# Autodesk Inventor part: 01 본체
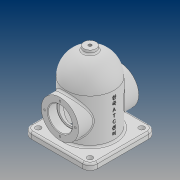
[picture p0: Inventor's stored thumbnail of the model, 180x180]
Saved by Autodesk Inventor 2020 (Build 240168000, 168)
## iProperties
Created: 2021-08
Part Number: 01 본체
Material: 일반
Document SubType Name: Modeling
Designer: PC312-
Density: 1 g/cm^3
Appearance: 기본값
Author: PC312-
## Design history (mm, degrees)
sketch "스케치1"
  geometry: C1 r 40 at (0, 0); 1 further point
  constraints: 1 centre point, 1 coincident
  dimensions: "d0" = 80 diameter of C1
extrude "돌출1" new body sketch "스케치1" distance "d1" = 124; taper "d2" = 0 deg
sketch "스케치2"
  geometry: 1 further point
fillet "모깎기1" dims "d3" = 40
feature "쉘1" dims "d4" = 8
sketch "스케치3"
  geometry: L1 (55, 55)-(-55, 55); L2 (-55, 55)-(-55, -55); L3 (-55, -55)-(55, -55); L4 (55, -55)-(55, 55); L5 (55, 55)-(-55, -55); L6 (-55, 55)-(55, -55); C1 r 40 at (0, 0) reference; 1 further point
  constraints: 12 end point, 2 midpoint, 2 parallel, 1 horizontal, 1 perpendicular
  dimensions: "d5" = 110 distance between parallel lines of L2 L4; "d6" = 110 distance between parallel lines of L3 L1
extrude "돌출2" join sketch "스케치3" distance "d7" = 10; taper "d8" = 0 deg
node "작업 평면1"
sketch "스케치4"
  geometry: L1 (55, 0)-(-55, 0) reference; C1 r 31 at (0, 48); 2 further points
  constraints: 1 centre point, 1 midpoint, 1 vertical alignment
  dimensions: "d10" = 62 diameter of C1; "d11" = 48 distance from line of C1.centre L1
extrude "돌출3" join sketch "스케치4" stored distance "d12" = 10; taper "d13" = 0 deg
sketch "스케치5"
  geometry: C1 r 20 at (0, 0); C2 r 31 at (0, 0) reference; 1 further point
  constraints: 1 centre point, 1 concentric
  dimensions: "d14" = 40 diameter of C1
extrude "돌출4" cut sketch "스케치5" distance "d15" = 15; taper "d16" = 0 deg
sketch "스케치6"
  geometry: C1 r 16.5 at (0, 0); C2 r 20 at (0, 0) reference; 1 further point
  constraints: 1 centre point, 1 concentric
  dimensions: "d17" = 33 diameter of C1
extrude "돌출5" cut sketch "스케치6" extent not by distance; stored distance "d18" = 15; taper "d19" = 0 deg
sketch "스케치7"
  geometry: L1 (55, -48)-(-55, -48) reference; C1 r 31 at (0, 0) reference; 3 further points
  constraints: 1 midpoint, 1 vertical alignment
  dimensions: "d20" = 25.5 distance of C1.centre point (0, 25.5)
hole "구멍1" sketch "스케치7" at (0, 25.5) diameter "d21" = 3.242; stored, may be unused: countersink angle "d25" = 90 deg, drill point angle "d27" = 118 deg; dims "d22" = 8, "d23" = 4, "d24" = 2, "d26" = 10
node "작업 평면2"
sketch "스케치8"
  geometry: C1 r 10 at (0, 0); 1 further point
  constraints: 1 centre point, 1 coincident
  dimensions: "d32" = 20 diameter of C1
extrude "돌출6" join sketch "스케치8" stored distance "d33" = 15; taper "d34" = 0 deg
sketch "스케치9"
  geometry: C1 r 10 at (0, 0) reference; 2 further points
  constraints: 1 coincident
hole "구멍2" sketch "스케치9" at (0, 0) diameter "d35" = 5.1881; stored, may be unused: countersink angle "d39" = 90 deg, drill point angle "d41" = 0 deg; dims "d36" = 12, "d37" = 4, "d38" = 2, "d40" = 70
sketch "스케치10"
  geometry: L1 (55, 55)-(-55, 55) reference; L2 (-55, 55)-(-55, -55) reference; C1 r 4.5 at (-43, 43); 1 further point
  constraints: 1 centre point
  dimensions: "d42" = 9 diameter of C1; "d43" = 12 distance from line of C1.centre L1; "d44" = 12 distance from line of C1.centre L2
extrude "돌출7" cut sketch "스케치10" extent not by distance; stored distance "d45" = 0; taper "d46" = 0 deg
fillet "모깎기2" dims "d53" = 12
fillet "모깎기3" dims "d54" = 3
fillet "모깎기4" dims "d55" = 3
fillet "모깎기5" dims "d56" = 0.3
chamfer "모따기1" distance "d57" = 1; stored, may be unused: second distance "d58" = 2, angle "d59" = 45 deg
node "작업 평면3"
sketch "스케치11"
  geometry: L1 (0, -43)-(0, 43) reference; 2 further points
  constraints: 1 horizontal alignment, 1 other
  dimensions: "d61" = 48 distance from line of point (48, 0) L1
feature "엠보싱1" sketch "스케치11" dims "d1" = 124, "d2" = 0, "d62" = 0.5, "d63" = 0
node "솔리드1"
pattern_circular "원형 패턴1" dims angle "d29" = 360 deg
mirror "미러1"
pattern_linear "직사각형 패턴1" dims "d49" = 86, "d52" = 86
feature "A9D066F2-1C7D-4E18-AEED-F7BC21143FA4" dims "d21" = 3.242, "d22" = 8, "d23" = 4, "d24" = 2, "d25" = 90 deg, "d26" = 10, "d27" = 118 deg
other parameters: "d31" = -129, "d60" = 66.5
